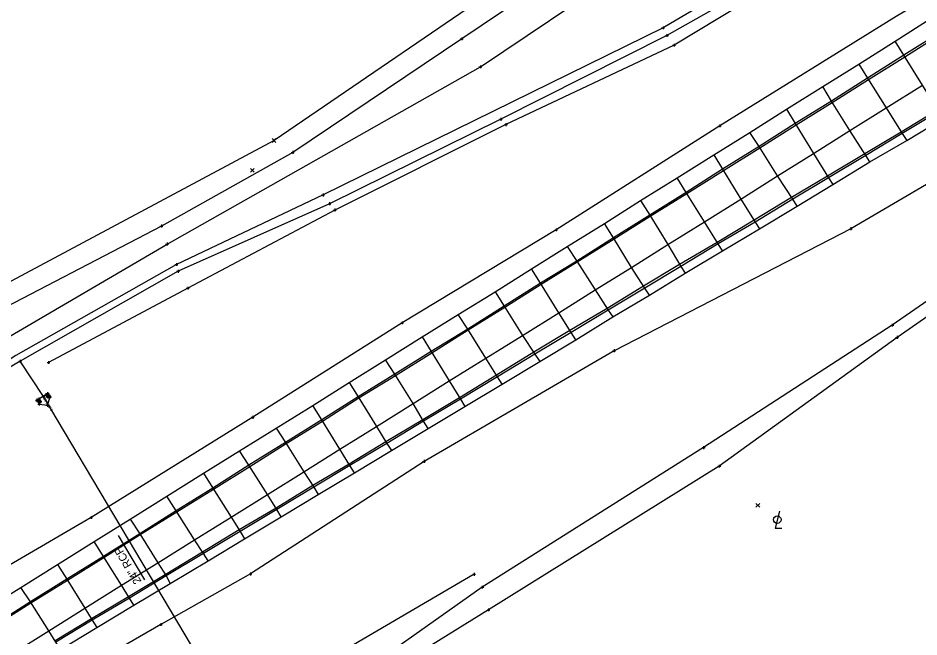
# Model space of a CAD drawing. Extents: x 207090 to 277928, y 600777 to 621109.
# Drawn here: x 260128.7 to 260443.9, y 612310 to 612526.4 of the extents above; entities that cross this region are included whole.
import ezdxf

# ---------------------------------------------------------------- set-up
doc = ezdxf.new("R2010")
doc.units = 0
for name, color, linetype in [('ATDIMS', 7, 'Continuous'), ('DR_X_Ditch', 7, 'Continuous'), ('DR_X_Headwall', 7, 'Continuous'), ('DR_X_Storm_Sewer', 7, 'Continuous'), ('DR_X_Text', 7, 'Continuous'), ('LT_X_Poles', 7, 'Continuous'), ('PM_P_Edge_Line', 7, 'Continuous'), ('PM_P_Lane_Line', 7, 'Continuous'), ('PM_P_Stop_Line', 7, 'Continuous'), ('PM_X_Edge_Line', 7, 'Continuous'), ('PV_X_EOP', 7, 'Continuous'), ('PV_X_Joint', 7, 'Continuous'), ('SC_ProfileRun2', 7, 'Continuous'), ('SV_X_Break_Lines', 7, 'Continuous'), ('SV_X_Terrain_Boundary', 7, 'Continuous'), ('SV_X_Toe_of_Slope', 7, 'Continuous')]:
    doc.layers.add(name, color=color, linetype=linetype)

msp = doc.modelspace()

# ---------------------------------------------------------------- linework, layer by layer
at = {"layer": 'DR_X_Ditch'}
for points in [[(260965.76, 612646.3), (260903.89, 612637.59), (260846.21, 612640.66), (260788.21, 612648.32), (260712.08, 612649.13), (260650.53, 612639.93), (260587.71, 612626.03), (260540.4, 612612.72), (260479.82, 612585.9), (260420.03, 612556.72), (260355.72, 612520.34), (260297.57, 612491.05), (260237.63, 612461.5), (260184.65, 612437.88), (260129.42, 612406.42), (260102.9, 612390.57), (260048.34, 612353.6), (259987.69, 612317.19), (259901.67, 612280.03), (259846.55, 612257.32), (259766.99, 612243.21), (259700.14, 612233.86)], [(260980.17, 612470.92), (260981.01, 612514.45), (260979.66, 612549.25), (260978.64, 612555.37), (260908.69, 612562.28), (260843.91, 612565.34), (260762.22, 612565.34), (260693.51, 612556.33), (260617.41, 612526.56), (260561.75, 612499.61), (260504.79, 612467.62), (260434.56, 612419.04), (260368.56, 612376.23), (260291.11, 612327.46), (260243.23, 612293.63), (260221.27, 612279.24), (260214.19, 612277.7), (260205.93, 612279.66)], [(260137.52, 612394.05), (260129.42, 612406.42)]]:
    msp.add_lwpolyline(points, dxfattribs=at)
at = {"layer": 'DR_X_Headwall'}
for p, q in [((260139.64, 612394.15), (260139.21, 612394.9)), ((260136.04, 612392.11), (260135.41, 612392.64))]:
    msp.add_line(p, q, dxfattribs=at)
for points in [[(260139.21, 612394.9), (260138.64, 612394.46), (260139.1, 612393.91), (260139.64, 612394.15)], [(260135.41, 612392.64), (260136, 612393.06), (260136.53, 612392.32), (260136.04, 612392.11)]]:
    msp.add_lwpolyline(points, dxfattribs=at)
at = {"layer": 'DR_X_Storm_Sewer'}
msp.add_line((260205.25, 612280.38), (260137.52, 612394.05), dxfattribs=at)
at = {"layer": 'DR_X_Text'}
msp.add_line((260163.68, 612345.46), (260172.92, 612329.95), dxfattribs=at)
at = {"layer": 'LT_X_Poles'}
msp.add_lwpolyline([(260395.11, 612354.01), (260393.53, 612348.02), (260395.9, 612348.02)], dxfattribs=at)
msp.add_circle((260394.32, 612351.05), 1.3, dxfattribs=at)
at = {"layer": 'PM_P_Edge_Line'}
for points in [[(259696.19, 612249.37), (259765.47, 612259.57), (259838.8, 612280.72), (259895.42, 612296.27), (259981.86, 612326.52), (260044.12, 612359.9), (260097.15, 612394.53), (260124, 612414.15), (260180.79, 612447.41), (260290.45, 612509.39), (260339.08, 612542.14), (260411.33, 612573.42), (260464.85, 612610.64), (260533.51, 612630.82), (260578.81, 612648.35), (260650.05, 612658.82), (260707.7, 612667.46), (260792.67, 612670.85), (260847.64, 612666.05), (260906.75, 612659.27), (260964.74, 612649.27), (260965.76, 612646.3), (260968.73, 612643.36)], [(260968.73, 612643.36), (260902.74, 612623.34), (260846.31, 612624.57), (260788.34, 612627.98), (260717.27, 612628.63), (260652.8, 612617.17), (260594.62, 612604.25), (260547.65, 612587.51), (260494.06, 612561.48), (260435.88, 612526.99), (260374.24, 612488.77), (260316.93, 612452.38), (260263.05, 612419.87), (260210.79, 612386.85), (260154.25, 612351.81), (260072.66, 612304.2), (260017.02, 612269.09), (259922.67, 612223.96), (259862.48, 612201.08), (259773.94, 612184.08), (259709.47, 612174.19)], [(260996.77, 612473.28), (260998.48, 612548.29), (260988.85, 612564.56), (260906.86, 612575.54), (260845.98, 612579.97), (260758.62, 612581.58), (260693.48, 612576.37), (260609.06, 612545.38), (260552.2, 612527.51), (260484.57, 612490.49), (260420.05, 612452.77), (260337.19, 612410.11), (260270.71, 612371.43), (260210.01, 612332.07), (260178.64, 612314.39), (260129.43, 612285.91), (260084.69, 612259.04), (260045.01, 612227.43), (260009.91, 612199.93)], [(260976.29, 612470.03), (260970.41, 612512.82), (260969.69, 612547.81), (260964.96, 612546.01), (260907.75, 612553.29), (260842.6, 612550.07), (260764.48, 612554.75), (260693.91, 612550.19), (260623.11, 612514), (260563.35, 612494.47), (260507.46, 612464.18), (260436.22, 612414.79), (260374.03, 612369.76), (260293.26, 612319.49), (260245.08, 612289.62), (260217.93, 612273.45)]]:
    msp.add_lwpolyline(points, dxfattribs=at)
at = {"layer": 'PM_P_Lane_Line'}
msp.add_lwpolyline([(260938.98, 612687.53), (260905.67, 612669.26), (260848.25, 612675.38), (260795.41, 612680.92), (260704.93, 612686.62), (260648.32, 612680.48), (260579.89, 612672.71), (260529.06, 612649.65), (260401.46, 612592.11), (260375.93, 612580.54), (260334.15, 612552.98), (260283.92, 612519.17), (260224.77, 612479.46), (260178.82, 612453.71), (260087.02, 612406.01), (260035.98, 612379.41), (259972.28, 612348.23), (259887.97, 612316.7), (259832.19, 612304.21), (259761.95, 612288.66), (259689.59, 612272.72)], dxfattribs=at)
at = {"layer": 'PM_P_Stop_Line'}
for p, q in [((260354.36, 612523.53), (260354.36, 612522.53)), ((260353.86, 612523.03), (260354.86, 612523.03)), ((260354.36, 612523.03), (260354.36, 612523.03)), ((260355.22, 612520.34), (260356.22, 612520.34)), ((260355.72, 612520.84), (260355.72, 612519.84)), ((260355.72, 612520.34), (260355.72, 612520.34)), ((260283.42, 612519.17), (260284.42, 612519.17)), ((260283.92, 612519.67), (260283.92, 612518.67)), ((260283.92, 612519.17), (260283.92, 612519.17)), ((260358.19, 612517.47), (260358.19, 612516.47)), ((260357.69, 612516.97), (260358.69, 612516.97)), ((260358.19, 612516.97), (260358.19, 612516.97)), ((260289.95, 612509.39), (260290.95, 612509.39)), ((260290.45, 612509.89), (260290.45, 612508.89)), ((260290.45, 612509.39), (260290.45, 612509.39)), ((260297.07, 612491.05), (260298.07, 612491.05)), ((260297.57, 612491.55), (260297.57, 612490.55)), ((260297.57, 612491.05), (260297.57, 612491.05)), ((260298.89, 612489.18), (260299.89, 612489.18)), ((260299.39, 612489.68), (260299.39, 612488.68)), ((260299.39, 612489.18), (260299.39, 612489.18)), ((260373.74, 612488.77), (260374.74, 612488.77)), ((260374.24, 612489.27), (260374.24, 612488.27)), ((260374.24, 612488.77), (260374.24, 612488.77)), ((260224.27, 612479.46), (260225.27, 612479.46)), ((260224.77, 612479.96), (260224.77, 612478.96)), ((260224.77, 612479.46), (260224.77, 612479.46)), ((260234.88, 612464.57), (260235.88, 612464.57)), ((260235.38, 612465.07), (260235.38, 612464.07)), ((260235.38, 612464.57), (260235.38, 612464.57)), ((260237.13, 612461.5), (260238.13, 612461.5)), ((260237.63, 612462), (260237.63, 612461)), ((260237.63, 612461.5), (260237.63, 612461.5)), ((260238.97, 612459.31), (260239.97, 612459.31)), ((260239.47, 612459.81), (260239.47, 612458.81)), ((260239.47, 612459.31), (260239.47, 612459.31)), ((260178.82, 612454.21), (260178.82, 612453.21)), ((260178.32, 612453.71), (260179.32, 612453.71)), ((260178.82, 612453.71), (260178.82, 612453.71)), ((260316.43, 612452.38), (260317.43, 612452.38)), ((260316.93, 612452.88), (260316.93, 612451.88)), ((260316.93, 612452.38), (260316.93, 612452.38)), ((260419.55, 612452.77), (260420.55, 612452.77)), ((260420.05, 612453.27), (260420.05, 612452.27)), ((260420.05, 612452.77), (260420.05, 612452.77)), ((260180.79, 612447.91), (260180.79, 612446.91)), ((260180.29, 612447.41), (260181.29, 612447.41)), ((260180.79, 612447.41), (260180.79, 612447.41)), ((260183.57, 612440.26), (260184.57, 612440.26)), ((260184.07, 612440.76), (260184.07, 612439.76)), ((260184.07, 612440.26), (260184.07, 612440.26)), ((260184.65, 612438.38), (260184.65, 612437.38)), ((260184.15, 612437.88), (260185.15, 612437.88)), ((260184.65, 612437.88), (260184.65, 612437.88)), ((260187.54, 612432.01), (260188.54, 612432.01)), ((260188.04, 612432.51), (260188.04, 612431.51)), ((260188.04, 612432.01), (260188.04, 612432.01)), ((260262.55, 612419.87), (260263.55, 612419.87)), ((260263.05, 612420.37), (260263.05, 612419.37)), ((260263.05, 612419.87), (260263.05, 612419.87)), ((260434.56, 612419.54), (260434.56, 612418.54)), ((260434.06, 612419.04), (260435.06, 612419.04)), ((260434.56, 612419.04), (260434.56, 612419.04)), ((260435.72, 612414.79), (260436.72, 612414.79)), ((260436.22, 612415.29), (260436.22, 612414.29)), ((260436.22, 612414.79), (260436.22, 612414.79)), ((260336.69, 612410.11), (260337.69, 612410.11)), ((260337.19, 612410.61), (260337.19, 612409.61)), ((260337.19, 612410.11), (260337.19, 612410.11)), ((260129.42, 612406.92), (260129.42, 612405.92)), ((260128.92, 612406.42), (260129.92, 612406.42)), ((260129.42, 612406.42), (260129.42, 612406.42)), ((260138.81, 612405.97), (260139.81, 612405.97)), ((260139.31, 612406.47), (260139.31, 612405.47)), ((260139.31, 612405.97), (260139.31, 612405.97)), ((260137.92, 612394.74), (260138.92, 612394.74)), ((260138.14, 612394.46), (260139.14, 612394.46)), ((260138.42, 612395.24), (260138.42, 612394.24)), ((260138.42, 612394.74), (260138.42, 612394.74)), ((260138.5, 612395.13), (260139.5, 612395.13)), ((260138.64, 612394.96), (260138.64, 612393.96)), ((260138.64, 612394.46), (260138.64, 612394.46)), ((260138.71, 612394.9), (260139.71, 612394.9)), ((260139, 612395.63), (260139, 612394.63)), ((260139, 612395.13), (260139, 612395.13)), ((260139.1, 612394.41), (260139.1, 612393.41)), ((260139.14, 612394.15), (260140.14, 612394.15)), ((260139.21, 612395.4), (260139.21, 612394.4)), ((260139.21, 612394.9), (260139.21, 612394.9)), ((260139.64, 612394.65), (260139.64, 612393.65)), ((260139.64, 612394.15), (260139.64, 612394.15)), ((260139.91, 612394.49), (260139.91, 612393.49)), ((260134.74, 612392.86), (260135.74, 612392.86)), ((260134.91, 612392.64), (260135.91, 612392.64)), ((260135.24, 612393.36), (260135.24, 612392.36)), ((260135.24, 612392.86), (260135.24, 612392.86)), ((260135.41, 612393.14), (260135.41, 612392.14)), ((260135.41, 612392.64), (260135.41, 612392.64)), ((260135.43, 612393.22), (260136.43, 612393.22)), ((260135.5, 612393.06), (260136.5, 612393.06)), ((260135.54, 612392.11), (260136.54, 612392.11)), ((260135.55, 612391.48), (260136.55, 612391.48)), ((260135.93, 612393.72), (260135.93, 612392.72)), ((260135.93, 612393.22), (260135.93, 612393.22)), ((260136, 612393.56), (260136, 612392.56)), ((260136, 612393.06), (260136, 612393.06)), ((260136.03, 612392.32), (260137.03, 612392.32)), ((260136.04, 612392.61), (260136.04, 612391.61)), ((260136.04, 612392.11), (260136.04, 612392.11)), ((260136.05, 612391.98), (260136.05, 612390.98)), ((260136.05, 612391.48), (260136.05, 612391.48)), ((260136.53, 612392.82), (260136.53, 612391.82)), ((260136.53, 612392.32), (260136.53, 612392.32)), ((260138.43, 612391.05), (260139.43, 612391.05)), ((260138.6, 612393.91), (260139.6, 612393.91)), ((260138.93, 612391.55), (260138.93, 612390.55)), ((260138.93, 612391.05), (260138.93, 612391.05)), ((260139.1, 612393.91), (260139.1, 612393.91)), ((260139.41, 612393.99), (260140.41, 612393.99)), ((260139.91, 612393.99), (260139.91, 612393.99)), ((260210.29, 612386.85), (260211.29, 612386.85)), ((260210.79, 612387.35), (260210.79, 612386.35)), ((260210.79, 612386.85), (260210.79, 612386.85)), ((260368.06, 612376.23), (260369.06, 612376.23)), ((260368.56, 612376.73), (260368.56, 612375.73)), ((260368.56, 612376.23), (260368.56, 612376.23)), ((260270.21, 612371.43), (260271.21, 612371.43)), ((260270.71, 612371.93), (260270.71, 612370.93)), ((260270.71, 612371.43), (260270.71, 612371.43)), ((260373.53, 612369.76), (260374.53, 612369.76)), ((260374.03, 612370.26), (260374.03, 612369.26)), ((260374.03, 612369.76), (260374.03, 612369.76)), ((260153.75, 612351.81), (260154.75, 612351.81)), ((260154.25, 612352.31), (260154.25, 612351.31)), ((260154.25, 612351.81), (260154.25, 612351.81)), ((260209.51, 612332.07), (260210.51, 612332.07)), ((260210.01, 612332.57), (260210.01, 612331.57)), ((260210.01, 612332.07), (260210.01, 612332.07)), ((260287.75, 612331.94), (260288.75, 612331.94)), ((260288.25, 612332.44), (260288.25, 612331.44)), ((260288.25, 612331.94), (260288.25, 612331.94)), ((260291.11, 612327.96), (260291.11, 612326.96)), ((260290.61, 612327.46), (260291.61, 612327.46)), ((260291.11, 612327.46), (260291.11, 612327.46)), ((260292.76, 612319.49), (260293.76, 612319.49)), ((260293.26, 612319.99), (260293.26, 612318.99)), ((260293.26, 612319.49), (260293.26, 612319.49)), ((260178.14, 612314.39), (260179.14, 612314.39)), ((260178.64, 612314.89), (260178.64, 612313.89)), ((260178.64, 612314.39), (260178.64, 612314.39))]:
    msp.add_line(p, q, dxfattribs=at)
at = {"layer": 'PM_X_Edge_Line'}
for p, q in [((260217.56, 612482.94), (260218.89, 612484.28)), ((260217.56, 612484.28), (260218.89, 612482.94)), ((260209.99, 612472.53), (260211.33, 612473.86)), ((260209.99, 612473.86), (260211.33, 612472.53)), ((260386.84, 612355.37), (260388.17, 612356.7)), ((260386.84, 612356.7), (260388.17, 612355.37))]:
    msp.add_line(p, q, dxfattribs=at)
for points in [[(260120.5, 612314.04), (260133.19, 612321.98), (260145.97, 612329.84), (260158.74, 612337.86), (260171.43, 612345.82), (260184.21, 612353.79), (260197.04, 612361.71), (260209.72, 612369.66), (260222.48, 612377.7), (260235.17, 612385.52), (260247.93, 612393.61), (260260.77, 612401.44), (260273.49, 612409.38), (260286.2, 612417.36), (260298.94, 612425.38), (260311.67, 612433.34), (260324.34, 612441.24), (260337.21, 612449.2), (260349.86, 612457.17), (260362.67, 612465.09), (260375.49, 612473.14), (260388.22, 612481.04), (260400.9, 612489.06), (260413.52, 612496.94), (260426.25, 612504.91), (260438.93, 612512.92), (260451.68, 612520.87)], [(260450.47, 612494.35), (260437.67, 612486.59), (260424.94, 612478.97), (260411.88, 612471.19), (260399.33, 612463.64), (260386.24, 612455.75), (260373.31, 612448.01), (260360.16, 612440.24), (260347.5, 612432.67), (260334.83, 612424.86), (260321.76, 612417.15), (260309.08, 612409.57), (260296.1, 612401.54), (260283.14, 612393.69), (260270.31, 612385.93), (260257.36, 612378.22), (260244.49, 612370.43), (260231.76, 612362.95), (260218.93, 612355.05), (260206.01, 612347.45), (260193.23, 612339.63), (260180.19, 612331.77), (260167.36, 612324.09), (260154.37, 612316.33), (260141.62, 612308.67)]]:
    msp.add_lwpolyline(points, dxfattribs=at)
at = {"layer": 'PV_X_EOP'}
for points in [[(260116.92, 612319.48), (260129.68, 612327.37), (260142.42, 612335.33), (260155.28, 612343.37), (260167.92, 612351.27), (260180.74, 612359.29), (260193.56, 612367.28), (260206.19, 612375.13), (260219.01, 612383.09), (260231.77, 612391.01), (260244.54, 612398.99), (260257.26, 612406.95), (260270.08, 612414.92), (260282.71, 612422.8), (260295.59, 612430.76), (260308.31, 612438.72), (260320.84, 612446.56), (260333.85, 612454.62), (260346.5, 612462.6), (260359.29, 612470.53), (260372.12, 612478.56), (260384.76, 612486.47), (260397.56, 612494.57), (260410.2, 612502.46), (260422.83, 612510.35), (260435.51, 612518.34), (260448.19, 612526.39)], [(260143.47, 612305.66), (260156.28, 612313.32), (260169.21, 612321.13), (260181.95, 612328.74), (260195.2, 612336.69), (260207.92, 612344.32), (260220.78, 612352.06), (260233.67, 612359.79), (260246.39, 612367.46), (260259.28, 612375.28), (260272.17, 612382.92), (260284.98, 612390.66), (260298, 612398.44), (260311.18, 612406.4), (260323.8, 612413.92), (260336.8, 612421.91), (260349.58, 612429.48), (260362.06, 612437.2), (260375.15, 612445.09), (260388.11, 612452.74), (260401.31, 612460.69), (260413.75, 612468.26), (260426.73, 612476.21), (260439.61, 612483.66), (260452.33, 612491.36)]]:
    msp.add_lwpolyline(points, dxfattribs=at)
at = {"layer": 'PV_X_Joint'}
for points in [[(260451.34, 612521.41), (260438.64, 612513.4), (260425.9, 612505.47), (260413.24, 612497.39), (260400.6, 612489.55), (260387.93, 612481.51), (260375.19, 612473.63)], [(260452.33, 612491.36), (260450.83, 612493.77), (260445.08, 612503), (260438.64, 612513.4), (260435.51, 612518.34)], [(260422.83, 612510.35), (260425.9, 612505.47), (260432.43, 612495), (260438, 612486.06), (260439.61, 612483.66)], [(260126.73, 612304.22), (260139.48, 612312.18), (260152.08, 612320.08), (260164.9, 612328.12), (260177.56, 612335.99), (260190.41, 612344), (260203.21, 612351.96), (260215.95, 612359.82), (260228.67, 612367.8), (260241.25, 612375.69), (260254.06, 612383.63), (260266.86, 612391.62), (260279.57, 612399.56), (260292.3, 612407.52), (260305.21, 612415.45), (260317.83, 612423.4), (260330.58, 612431.38), (260343.29, 612439.27), (260355.97, 612447.2), (260368.8, 612455.23), (260381.58, 612463.15), (260394.44, 612471.21), (260406.96, 612479.12), (260419.75, 612487.16), (260432.43, 612495), (260445.08, 612503)], [(260426.73, 612476.21), (260425.31, 612478.39), (260419.75, 612487.16), (260413.24, 612497.39), (260410.2, 612502.46)], [(260450.83, 612493.77), (260438, 612486.06), (260425.31, 612478.39), (260412.26, 612470.58), (260399.71, 612463.06), (260386.63, 612455.12), (260373.67, 612447.43), (260360.59, 612439.52), (260347.94, 612431.97), (260335.18, 612424.32), (260322.16, 612416.5), (260309.53, 612408.9), (260296.46, 612400.97), (260283.47, 612393.15), (260270.59, 612385.47), (260257.69, 612377.7), (260244.77, 612369.98), (260232.12, 612362.39), (260219.18, 612354.64), (260206.36, 612346.88), (260193.5, 612339.22), (260180.44, 612331.37), (260167.64, 612323.64), (260154.64, 612315.89), (260141.92, 612308.17)], [(260397.56, 612494.57), (260400.6, 612489.55), (260406.96, 612479.12), (260412.26, 612470.58), (260413.75, 612468.26)], [(260401.31, 612460.69), (260399.71, 612463.06), (260394.44, 612471.21), (260387.93, 612481.51), (260384.76, 612486.47)], [(260372.12, 612478.56), (260375.19, 612473.63), (260381.58, 612463.15), (260386.63, 612455.12), (260388.11, 612452.74)], [(260375.19, 612473.63), (260362.48, 612465.39), (260349.67, 612457.48), (260337.01, 612449.53), (260324.22, 612441.42), (260311.46, 612433.68), (260298.71, 612425.75), (260286, 612417.68), (260273.2, 612409.85), (260260.51, 612401.87), (260247.73, 612393.94), (260234.91, 612385.95), (260222.25, 612378.07), (260209.43, 612370.13), (260196.79, 612362.09), (260184, 612354.12), (260171.24, 612346.13), (260158.52, 612338.21), (260145.73, 612330.23), (260133.01, 612322.27), (260120.34, 612314.28)], [(260375.15, 612445.09), (260373.67, 612447.43), (260368.8, 612455.23), (260362.48, 612465.39), (260359.29, 612470.53)], [(260346.5, 612462.6), (260349.67, 612457.48), (260355.97, 612447.2), (260360.59, 612439.52), (260362.06, 612437.2)], [(260349.58, 612429.48), (260347.94, 612431.97), (260343.29, 612439.27), (260337.01, 612449.53), (260333.85, 612454.62)], [(260320.84, 612446.56), (260324.22, 612441.42), (260330.58, 612431.38), (260335.18, 612424.32), (260336.8, 612421.91)], [(260323.8, 612413.92), (260322.16, 612416.5), (260317.83, 612423.4), (260311.46, 612433.68), (260308.31, 612438.72)], [(260295.59, 612430.76), (260298.71, 612425.75), (260305.21, 612415.45), (260309.53, 612408.9), (260311.18, 612406.4)], [(260298, 612398.44), (260296.46, 612400.97), (260292.3, 612407.52), (260286, 612417.68), (260282.71, 612422.8)], [(260270.08, 612414.92), (260273.2, 612409.85), (260279.57, 612399.56), (260283.47, 612393.15), (260284.98, 612390.66)], [(260272.17, 612382.92), (260270.59, 612385.47), (260266.86, 612391.62), (260260.51, 612401.87), (260257.26, 612406.95)], [(260244.54, 612398.99), (260247.73, 612393.94), (260254.06, 612383.63), (260257.69, 612377.7), (260259.28, 612375.28)], [(260246.39, 612367.46), (260244.77, 612369.98), (260241.25, 612375.69), (260234.91, 612385.95), (260231.77, 612391.01)], [(260219.01, 612383.09), (260222.25, 612378.07), (260228.67, 612367.8), (260232.12, 612362.39), (260233.67, 612359.79)], [(260220.78, 612352.06), (260219.18, 612354.64), (260215.95, 612359.82), (260209.43, 612370.13), (260206.19, 612375.13)], [(260193.56, 612367.28), (260196.79, 612362.09), (260203.21, 612351.96), (260206.36, 612346.88), (260207.92, 612344.32)], [(260195.2, 612336.69), (260193.5, 612339.22), (260190.41, 612344), (260184, 612354.12), (260180.74, 612359.29)], [(260167.92, 612351.27), (260171.24, 612346.13), (260177.56, 612335.99), (260180.44, 612331.37), (260181.95, 612328.74)], [(260169.21, 612321.13), (260167.64, 612323.64), (260164.9, 612328.12), (260158.52, 612338.21), (260155.28, 612343.37)], [(260142.42, 612335.33), (260145.73, 612330.23), (260152.08, 612320.08), (260154.64, 612315.89), (260156.28, 612313.32)], [(260143.47, 612305.66), (260141.92, 612308.17), (260139.48, 612312.18), (260133.01, 612322.27), (260129.68, 612327.37)]]:
    msp.add_lwpolyline(points, dxfattribs=at)
at = {"layer": 'SC_ProfileRun2'}
for p, q in [((260137.02, 612394.05), (260138.02, 612394.05)), ((260137.52, 612394.55), (260137.52, 612393.55)), ((260137.52, 612394.05), (260137.52, 612394.05))]:
    msp.add_line(p, q, dxfattribs=at)
at = {"layer": 'SV_X_Break_Lines'}
msp.add_lwpolyline([(260135.93, 612393.22), (260135.24, 612392.86), (260136.05, 612391.48), (260138.93, 612391.05), (260139.91, 612393.99), (260139, 612395.13), (260138.42, 612394.74)], close=True, dxfattribs=at)
at = {"layer": 'SV_X_Terrain_Boundary'}
msp.add_lwpolyline([(260983.37, 612812.65), (260938.98, 612687.53), (260903.8, 612676.08), (260828.62, 612686.24), (260720.8, 612697.94), (260579.24, 612680.21), (260471.8, 612633.29), (260370.94, 612586.63), (260308.24, 612545.06), (260218.23, 612483.61), (260121.1, 612431.7), (260019.22, 612378.89), (259908.73, 612332.42)], dxfattribs=at)
at = {"layer": 'SV_X_Toe_of_Slope'}
for points in [[(260846.78, 612643.82), (260788.62, 612651.68), (260711.88, 612651.68), (260649.51, 612644.01), (260586.77, 612629.44), (260538.54, 612616.8), (260477.73, 612589.44), (260417.65, 612560.33), (260354.36, 612523.03), (260235.38, 612464.57), (260184.07, 612440.26), (260127.9, 612408.42), (260047.32, 612354.89), (259986.34, 612321), (259898.57, 612287.97), (259845.49, 612261.31), (259767.02, 612246.06), (259699.57, 612235.7)], [(260846.79, 612637.04), (260787.74, 612645.4), (260713.66, 612644.84), (260650.44, 612637.88), (260588.47, 612623.19), (260541.01, 612608.57), (260480.87, 612584.7), (260421.09, 612554.93), (260358.19, 612516.97), (260299.39, 612489.18), (260239.47, 612459.31), (260188.04, 612432.01), (260139.31, 612405.97)], [(260288.25, 612331.94), (260236.48, 612301.69), (260209.62, 612282.46)]]:
    msp.add_lwpolyline(points, dxfattribs=at)

# ---------------------------------------------------------------- texts
at = {"layer": 'ATDIMS'}
msp.add_text("1,127.32'", height=1, rotation=120.7903, dxfattribs=at).set_placement((260140.91, 612389.34))
at = {"layer": 'DR_X_Text'}
msp.add_text('24" RCP', height=2.8, rotation=120.7903, dxfattribs=at).set_placement((260171.92, 612329.49))

doc.saveas('drawing.dxf')
